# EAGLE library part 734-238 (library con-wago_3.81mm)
Serie 734, Stiftleiste (für Leiterplatten) Einlötstift gerade 1 x 1 mm / Series 734, Male header (for PCBs) Straight solder pin 1 x 1 mm Polzahl / Pole No.: 8 Rastermaß / Pitch: 3.81 mm Bemessungsspannung / Rated Voltage: 160 V Nennstrom / Nominal Current: 10 A Lötstiftlänge: / Solder Pin Length: 4.5 mm Farbe / Color: orange / orange Stand: 01.01.2012. Die jeweils aktuellen Daten zu diesem Artikel finden Sie in unserem Produktkatalog, den Sie unter www.wago.com einsehen können. As of: 01/01/2012. Please find the newest data for this article in our product catalogue, which can be viewed under www.wago.com.
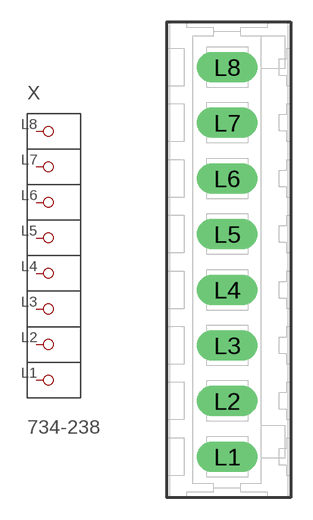
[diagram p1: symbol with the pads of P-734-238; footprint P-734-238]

Designator prefix X

## 734-238  [P-734-238]
L1  P1
L2  P2
L3  P3
L4  P4
L5  P5
L6  P6
L7  P7
L8  P8

## Footprint P-734-238 (pad centres in mm)
drill 1.4 long: L1 -0.1,-13.485; L2 -0.1,-9.675; L3 -0.1,-5.865; L4 -0.1,-2.055; L5 -0.1,1.755; L6 -0.1,5.565; L7 -0.1,9.375; L8 -0.1,13.185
